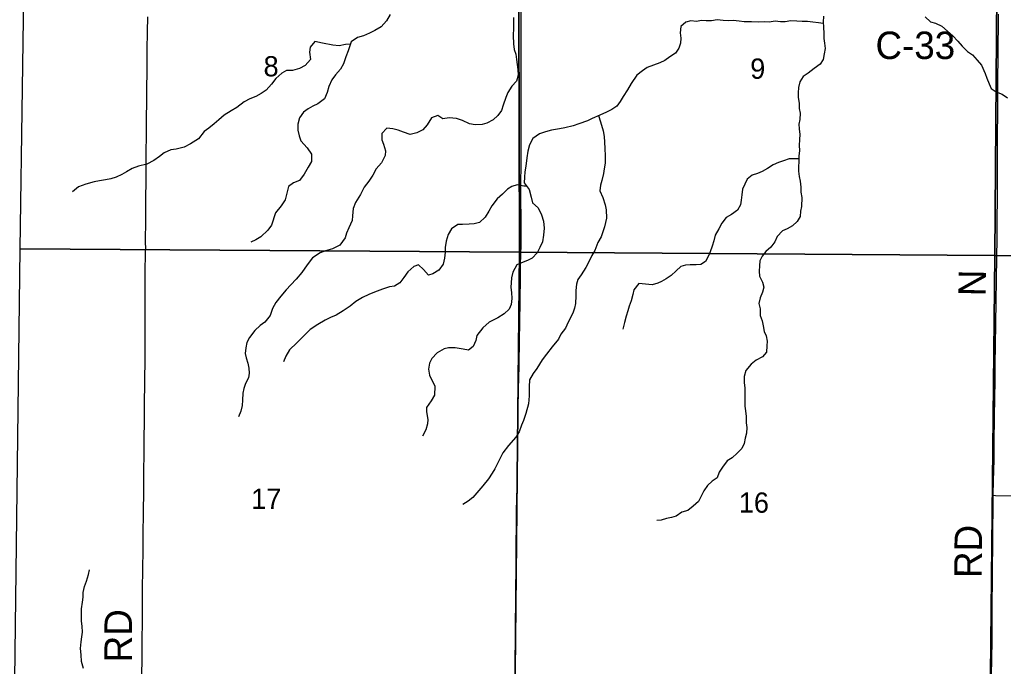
# Model space of a CAD drawing. Extents: x 1584893 to 1934202, y 663575 to 1091909.
# Drawn here: x 1718571 to 1729310, y 949050 to 956109 of the extents above; entities that cross this region are included whole.
import ezdxf

# ---------------------------------------------------------------- set-up
doc = ezdxf.new("R2010")
doc.units = 0
for name, color, linetype in [('GM_X_County_Road', 7, 'Continuous'), ('GM_X_County_Road_Text', 7, 'Continuous'), ('GM_X_Minor_River', 7, 'Continuous'), ('GM_X_Section', 7, 'Continuous'), ('GM_X_Section_Text', 7, 'Continuous'), ('GM_X_State_Route', 7, 'Continuous'), ('GM_X_Township_Road', 7, 'Continuous'), ('GM_X_Township_Road_Text', 7, 'Continuous')]:
    doc.layers.add(name, color=color, linetype=linetype)

msp = doc.modelspace()

# ---------------------------------------------------------------- linework, layer by layer
at = {"layer": 'GM_X_County_Road'}
msp.add_lwpolyline([(1729200, 950917), (1729224, 950916), (1729595, 950912), (1729776, 950909), (1729973, 950906), (1730153, 950903), (1730464, 950899), (1730710, 950896), (1730923, 950895), (1731169, 950892), (1731481, 950888), (1731760, 950883), (1731907, 950882), (1732252, 950873), (1732349, 950871), (1732579, 950865), (1732906, 950862), (1733086, 950857), (1733250, 950853), (1733578, 950847), (1733988, 950839), (1734023, 950838)], dxfattribs=at)
at = {"layer": 'GM_X_Minor_River'}
for points in [[(1723964, 956132), (1723964, 956078), (1723962, 956015), (1723960, 955935), (1723963, 955847), (1723971, 955783), (1723987, 955733), (1723997, 955673), (1724001, 955620), (1724010, 955560), (1724012, 955502), (1723994, 955438), (1723946, 955384), (1723902, 955314), (1723878, 955260), (1723851, 955176), (1723831, 955118), (1723791, 955064), (1723739, 955016), (1723671, 954978), (1723621, 954966), (1723545, 954962), (1723483, 954973), (1723405, 955009), (1723339, 955029), (1723259, 955037), (1723193, 955028), (1723135, 955064), (1723069, 955038), (1723019, 954960), (1722973, 954908), (1722907, 954874), (1722833, 954856), (1722761, 954881), (1722703, 954903), (1722647, 954917), (1722581, 954923), (1722525, 954865), (1722524, 954799), (1722544, 954749), (1722566, 954677), (1722562, 954627), (1722520, 954547), (1722463, 954481), (1722427, 954411), (1722383, 954347), (1722333, 954279), (1722291, 954202), (1722238, 954112), (1722212, 954048), (1722204, 953968), (1722202, 953916), (1722165, 953838), (1722141, 953780), (1722125, 953726), (1722067, 953646), (1721985, 953606), (1721911, 953584), (1721853, 953562), (1721770, 953510), (1721710, 953434), (1721652, 953350), (1721590, 953276), (1721531, 953213), (1721479, 953159), (1721423, 953091), (1721369, 953023), (1721331, 952955), (1721306, 952878), (1721248, 952806), (1721198, 952769), (1721138, 952715), (1721080, 952639), (1721053, 952585), (1721041, 952526), (1721035, 952466), (1721045, 952416), (1721061, 952360), (1721073, 952304), (1721076, 952250), (1721068, 952198), (1721038, 952136), (1721018, 952084), (1721006, 952031)], [(1722617, 956166), (1722577, 956098), (1722519, 956032), (1722449, 955992), (1722391, 955962), (1722326, 955934), (1722258, 955915), (1722190, 955867), (1722156, 955769), (1722132, 955704), (1722106, 955626), (1722073, 955568), (1722021, 955506), (1721979, 955452), (1721945, 955378), (1721927, 955314), (1721900, 955246), (1721828, 955192), (1721772, 955164), (1721722, 955136), (1721670, 955098), (1721628, 955036), (1721607, 954970), (1721609, 954902), (1721621, 954842), (1721641, 954788), (1721711, 954711), (1721756, 954639), (1721756, 954559), (1721722, 954499), (1721676, 954423), (1721625, 954353), (1721561, 954327), (1721507, 954287), (1721493, 954229), (1721471, 954141), (1721428, 954077), (1721364, 953999), (1721320, 953867), (1721280, 953811), (1721205, 953737), (1721149, 953707), (1721095, 953681)], [(1727345, 956067), (1727293, 956074), (1727231, 956081), (1727173, 956090), (1727113, 956089), (1727057, 956094), (1726991, 956095), (1726928, 956086), (1726878, 956087), (1726818, 956092), (1726754, 956081), (1726698, 956084), (1726636, 956081), (1726560, 956086), (1726480, 956087), (1726426, 956092), (1726362, 956101), (1726306, 956098), (1726252, 956101), (1726186, 956108), (1726124, 956095), (1726066, 956098), (1726016, 956099), (1725959, 956090), (1725899, 956095), (1725845, 956082), (1725788, 956035), (1725783, 955965), (1725788, 955908), (1725785, 955852), (1725768, 955797), (1725731, 955743), (1725671, 955704), (1725616, 955665), (1725561, 955638), (1725559, 955636)], [(1727346, 956147), (1727345, 956081), (1727346, 956029), (1727351, 955953), (1727352, 955903), (1727359, 955852), (1727364, 955796), (1727355, 955736), (1727342, 955674), (1727309, 955623), (1727244, 955576), (1727178, 955525), (1727125, 955490), (1727090, 955430), (1727073, 955368), (1727070, 955312), (1727071, 955258), (1727080, 955196), (1727081, 955141), (1727092, 955087), (1727087, 955021), (1727078, 954967), (1727081, 954917), (1727088, 954855), (1727084, 954801), (1727080, 954737), (1727086, 954682), (1727079, 954618), (1727078, 954558), (1727073, 954506), (1727074, 954456), (1727083, 954396), (1727094, 954345), (1727101, 954281), (1727100, 954225), (1727109, 954169), (1727108, 954071), (1727097, 954017), (1727094, 953961), (1727059, 953907), (1727008, 953860), (1726951, 953825), (1726899, 953803), (1726842, 953742), (1726815, 953685), (1726772, 953625), (1726719, 953580), (1726676, 953526), (1726653, 953475), (1726650, 953421), (1726645, 953363), (1726648, 953308), (1726681, 953244), (1726697, 953189), (1726682, 953134), (1726655, 953074), (1726640, 953010), (1726655, 952954), (1726655, 952879), (1726676, 952823), (1726688, 952767), (1726699, 952706), (1726720, 952656), (1726731, 952600), (1726730, 952549), (1726725, 952479), (1726680, 952428), (1726613, 952391), (1726557, 952348), (1726501, 952281), (1726480, 952213), (1726481, 952145), (1726488, 952090), (1726487, 952034), (1726490, 951968), (1726489, 951890), (1726496, 951838), (1726503, 951777), (1726504, 951709), (1726509, 951657), (1726506, 951595), (1726493, 951541), (1726480, 951483), (1726455, 951429), (1726404, 951376), (1726349, 951327), (1726297, 951292), (1726244, 951224), (1726207, 951169), (1726186, 951109), (1726133, 951072)], [(1728457, 956139), (1728516, 956086), (1728570, 956071), (1728640, 956038), (1728701, 955985), (1728760, 955932), (1728813, 955873), (1728862, 955818), (1728920, 955761), (1728973, 955724), (1729026, 955667), (1729073, 955612), (1729112, 955523), (1729129, 955472), (1729156, 955410), (1729179, 955359), (1729231, 955320), (1729296, 955297), (1729356, 955254)], [(1722182, 955843), (1722130, 955839), (1722060, 955823), (1721992, 955829), (1721876, 955854), (1721794, 955870), (1721744, 955808), (1721734, 955754), (1721748, 955674), (1721690, 955610), (1721628, 955576), (1721549, 955554), (1721486, 955554), (1721433, 955526), (1721367, 955466), (1721321, 955406), (1721261, 955338), (1721209, 955302), (1721151, 955270), (1721083, 955243), (1721021, 955211), (1720942, 955151), (1720882, 955115), (1720804, 955065), (1720746, 955015), (1720696, 954971), (1720638, 954925), (1720584, 954889), (1720525, 954807), (1720435, 954752), (1720369, 954716), (1720279, 954694), (1720221, 954688), (1720149, 954656), (1720097, 954614), (1720035, 954572), (1719961, 954530), (1719867, 954511), (1719799, 954483), (1719736, 954447), (1719686, 954417), (1719624, 954391), (1719566, 954373), (1719508, 954359), (1719444, 954348), (1719384, 954340), (1719294, 954314), (1719214, 954284), (1719148, 954230)], [(1725559, 955636), (1725422, 955586), (1725372, 955552), (1725310, 955502), (1725249, 955414), (1725207, 955342), (1725161, 955270), (1725127, 955216), (1725091, 955164), (1725035, 955128), (1724977, 955100), (1724904, 955068), (1724820, 955031), (1724770, 955005), (1724676, 954973), (1724614, 954951), (1724524, 954929), (1724464, 954917), (1724376, 954902), (1724312, 954886), (1724248, 954862), (1724174, 954810), (1724136, 954744), (1724119, 954674), (1724107, 954600), (1724097, 954508), (1724087, 954449), (1724082, 954391), (1724078, 954327), (1724134, 954255), (1724154, 954173), (1724169, 954110), (1724231, 954054), (1724269, 953980), (1724289, 953910), (1724298, 953833), (1724292, 953755), (1724280, 953685), (1724252, 953621), (1724222, 953563), (1724167, 953507), (1724117, 953479), (1724049, 953455), (1723999, 953431), (1723955, 953351), (1723941, 953291), (1723934, 953185), (1723942, 953131), (1723946, 953065), (1723938, 953001), (1723914, 952947), (1723859, 952897), (1723791, 952855), (1723697, 952807), (1723627, 952745), (1723563, 952661), (1723553, 952607), (1723524, 952541), (1723472, 952501), (1723414, 952511), (1723326, 952527), (1723254, 952528), (1723204, 952516), (1723130, 952472), (1723070, 952412), (1723046, 952360), (1723034, 952294), (1723045, 952228), (1723105, 952107), (1723101, 952009), (1723064, 951947), (1723012, 951877), (1723012, 951827), (1723026, 951746), (1723022, 951696), (1723005, 951632), (1722969, 951562)], [(1724892, 955063), (1724912, 954994), (1724940, 954894), (1724952, 954834), (1724957, 954770), (1724961, 954703), (1724965, 954621), (1724963, 954543), (1724952, 954481), (1724944, 954429), (1724928, 954353), (1724912, 954301), (1724906, 954242), (1724937, 954166), (1724963, 954088), (1724975, 954034), (1724979, 953942), (1724958, 953849), (1724938, 953793), (1724918, 953739), (1724882, 953677), (1724849, 953589), (1724819, 953533), (1724793, 953481), (1724753, 953403), (1724700, 953323), (1724666, 953271), (1724652, 953221), (1724642, 953151), (1724644, 953093), (1724641, 953010), (1724629, 952960), (1724609, 952904), (1724559, 952808), (1724529, 952740), (1724480, 952674), (1724454, 952620), (1724386, 952538), (1724324, 952456), (1724277, 952396), (1724217, 952302), (1724179, 952248), (1724139, 952176), (1724135, 952102), (1724134, 952002), (1724126, 951917), (1724096, 951809), (1724071, 951735), (1724051, 951681), (1724023, 951609), (1723989, 951553), (1723908, 951461), (1723846, 951379), (1723788, 951263), (1723758, 951207), (1723729, 951157), (1723689, 951097), (1723629, 951021), (1723561, 950945), (1723517, 950893), (1723467, 950853), (1723410, 950817)], [(1727078, 954590), (1727024, 954591), (1726972, 954590), (1726911, 954567), (1726857, 954548), (1726799, 954523), (1726734, 954484), (1726677, 954451), (1726627, 954431), (1726569, 954412), (1726514, 954369), (1726487, 954313), (1726464, 954260), (1726455, 954198), (1726448, 954140), (1726441, 954088), (1726408, 954028), (1726341, 953981), (1726283, 953950), (1726237, 953889), (1726204, 953827), (1726163, 953757), (1726150, 953696), (1726131, 953638), (1726108, 953574), (1726087, 953522), (1726060, 953469), (1726008, 953437), (1725958, 953434), (1725892, 953433), (1725841, 953430), (1725791, 953413), (1725738, 953368), (1725683, 953318), (1725631, 953279), (1725580, 953252), (1725540, 953232)], [(1724107, 954290), (1724074, 954293), (1724004, 954307), (1723946, 954288), (1723896, 954260), (1723842, 954204), (1723786, 954154), (1723727, 954076), (1723695, 954018), (1723653, 953952), (1723593, 953896), (1723533, 953880), (1723477, 953878), (1723407, 953874), (1723355, 953872), (1723285, 953825), (1723249, 953762), (1723226, 953690), (1723218, 953622), (1723216, 953570), (1723210, 953504), (1723194, 953440), (1723147, 953374), (1723083, 953336), (1723033, 953320), (1722979, 953382), (1722926, 953433), (1722874, 953413), (1722809, 953355), (1722765, 953295), (1722721, 953235), (1722663, 953199), (1722609, 953191), (1722533, 953167), (1722445, 953136), (1722383, 953108), (1722313, 953076), (1722243, 953032), (1722178, 952980), (1722102, 952930), (1722026, 952884), (1721964, 952856), (1721908, 952830), (1721826, 952781), (1721744, 952725), (1721684, 952667), (1721597, 952583), (1721519, 952505), (1721477, 952437), (1721451, 952375)], [(1725540, 953232), (1725478, 953214), (1725402, 953221), (1725332, 953229), (1725278, 953159), (1725266, 953109), (1725247, 953039), (1725227, 952981), (1725211, 952930), (1725193, 952872), (1725173, 952802), (1725156, 952730)], [(1721006, 952031), (1721005, 951957), (1720999, 951897), (1720987, 951837), (1720959, 951775)], [(1726133, 951072), (1726080, 951023), (1726041, 950967), (1726008, 950900), (1725981, 950848), (1725924, 950797), (1725865, 950750), (1725801, 950731), (1725740, 950688), (1725688, 950674), (1725634, 950663), (1725575, 950646), (1725529, 950641)], [(1719270, 949026), (1719246, 949102), (1719241, 949174), (1719237, 949246), (1719241, 949317), (1719251, 949373), (1719259, 949423), (1719254, 949487), (1719246, 949543), (1719246, 949595), (1719248, 949679), (1719256, 949750), (1719263, 949804), (1719265, 949854), (1719279, 949922), (1719301, 949980), (1719323, 950052), (1719334, 950102)]]:
    msp.add_lwpolyline(points, dxfattribs=at)
at = {"layer": 'GM_X_Section'}
for points in [[(1724013, 958821), (1724030, 953572), (1718577, 953608), (1718653, 958873)], [(1729259, 958799), (1729219, 953534), (1724030, 953572), (1724013, 958821)], [(1729259, 958799), (1734451, 958724), (1734432, 953454), (1729219, 953534)], [(1718577, 953608), (1724030, 953572), (1723973, 948294), (1718513, 948322)], [(1724030, 953572), (1729219, 953534), (1729163, 948254), (1723973, 948294)], [(1729219, 953534), (1734432, 953454), (1734388, 948198), (1729163, 948254)]]:
    msp.add_lwpolyline(points, close=True, dxfattribs=at)
at = {"layer": 'GM_X_State_Route'}
msp.add_lwpolyline([(1724041, 956201), (1724042, 956061), (1724041, 955815), (1724041, 955586), (1724041, 955340), (1724042, 955159), (1724042, 954995), (1724042, 954798), (1724041, 954667), (1724041, 954520), (1724040, 954323), (1724040, 954191), (1724041, 953896), (1724041, 953749), (1724041, 953650), (1724037, 953437), (1724035, 953273), (1724033, 953060), (1724027, 952781), (1724025, 952633), (1724020, 952322), (1724013, 952076), (1724011, 951862), (1724005, 951567), (1724002, 951354), (1724000, 951190), (1723998, 951010), (1723995, 950878), (1723993, 950747), (1723993, 950665), (1723992, 950567), (1723989, 950403), (1723987, 950140), (1723985, 949861), (1723984, 949714), (1723982, 949550), (1723980, 949336), (1723979, 949123), (1723978, 948992)], dxfattribs=at)
at = {"layer": 'GM_X_Township_Road'}
for points in [[(1719905, 948920), (1719908, 949166), (1719910, 949347), (1719912, 949527), (1719913, 949724), (1719914, 949872), (1719917, 950134), (1719918, 950298), (1719919, 950380), (1719920, 950512), (1719924, 950709), (1719927, 950988), (1719928, 951135), (1719930, 951414), (1719930, 951546), (1719933, 951710), (1719935, 951923), (1719937, 952136), (1719941, 952432), (1719942, 952629), (1719942, 952760), (1719940, 953006), (1719941, 953121), (1719943, 953384), (1719946, 953531), (1719946, 953581), (1719947, 953630), (1719946, 953663), (1719945, 953712), (1719948, 953893), (1719950, 954122), (1719951, 954385), (1719952, 954516), (1719954, 954631), (1719956, 954877), (1719957, 955041), (1719960, 955206), (1719961, 955370), (1719962, 955534), (1719964, 955780), (1719967, 955977), (1719969, 956141)], [(1729200, 950917), (1729204, 951081), (1729207, 951180), (1729209, 951311), (1729210, 951508), (1729214, 951754), (1729218, 952000), (1729220, 952148), (1729222, 952361), (1729225, 952542), (1729227, 952804), (1729231, 953017), (1729236, 953280), (1729239, 953510), (1729242, 953723), (1729243, 953838), (1729244, 953985), (1729246, 954100), (1729246, 954246), (1729246, 954428), (1729248, 954740), (1729248, 954921), (1729249, 955019), (1729250, 955183), (1729250, 955347), (1729251, 955479), (1729254, 955676), (1729254, 955741), (1729255, 955790), (1729257, 956086), (1729257, 956168)], [(1729174, 948282), (1729174, 948294), (1729174, 948326), (1729178, 948522), (1729179, 948620), (1729183, 948949), (1729187, 949326), (1729188, 949457), (1729188, 949539), (1729189, 949605), (1729190, 949703), (1729190, 949736), (1729190, 949769), (1729190, 949834), (1729191, 949884), (1729193, 950179), (1729194, 950310), (1729195, 950359), (1729196, 950540), (1729197, 950589), (1729198, 950720), (1729199, 950884), (1729200, 950917)]]:
    msp.add_lwpolyline(points, dxfattribs=at)

# ---------------------------------------------------------------- texts
at = {"layer": 'GM_X_County_Road_Text'}
msp.add_text('C-33', height=300, rotation=0, dxfattribs=at).set_placement((1727915, 955679))
at = {"layer": 'GM_X_Section_Text'}
for s, p in [('8', (1721234, 955490)), ('9', (1726547, 955464)), ('17', (1721099, 950769)), ('16', (1726423, 950727))]:
    msp.add_text(s, height=221, rotation=0, dxfattribs=at).set_placement(p)
at = {"layer": 'GM_X_Township_Road_Text'}
for s, rotation, p in [('N', 89.1148, (1729118, 953088)), ('RD', 89.505, (1729074, 950013)), ('RD', 90, (1719797, 949094))]:
    msp.add_text(s, height=300, rotation=rotation, dxfattribs=at).set_placement(p)

doc.saveas('drawing.dxf')
